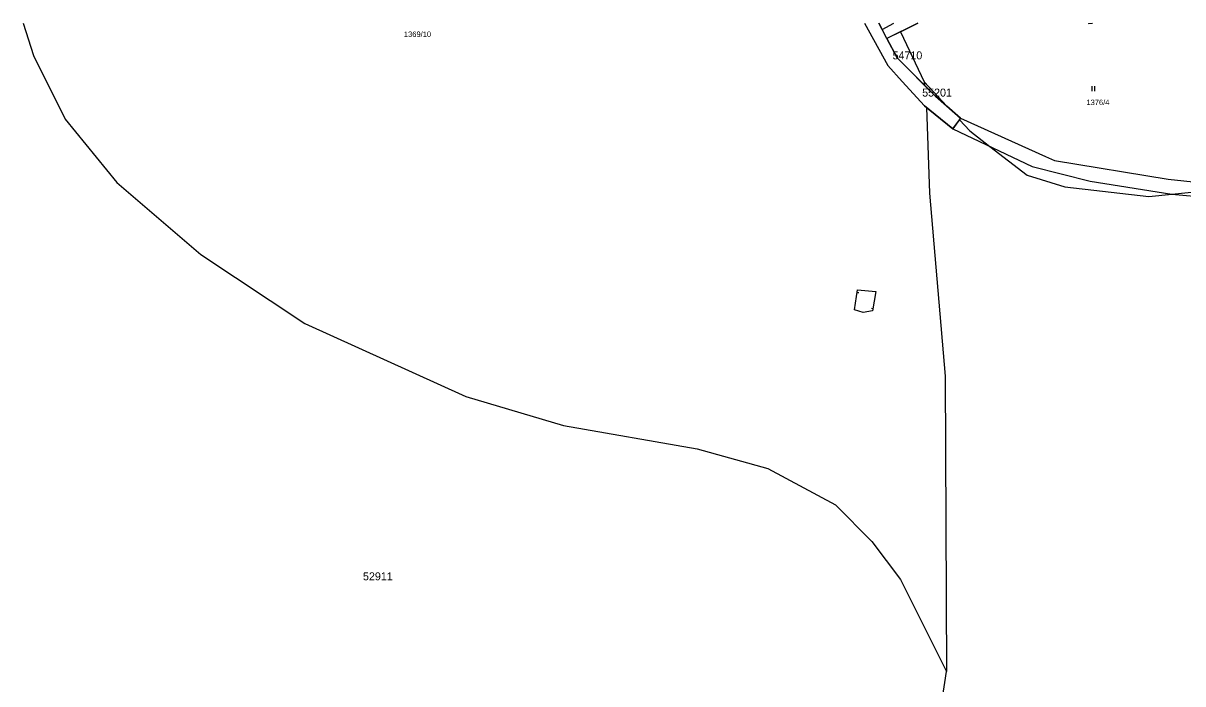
# Model space of a CAD drawing. Extents: x -779618 to -776429, y -1144546 to -1143350.
# Drawn here: x -778020.3 to -777658, y -1143556 to -1143349.7 of the extents above; entities that cross this region are included whole.
import ezdxf

# ---------------------------------------------------------------- set-up
doc = ezdxf.new("R2010")
doc.units = 0
for name, color, linetype in [('1', 7, 'Continuous'), ('11', 7, 'Continuous'), ('13', 7, 'Continuous'), ('2', 7, 'Continuous'), ('3', 7, 'Continuous')]:
    doc.layers.add(name, color=color, linetype=linetype)

msp = doc.modelspace()

# ---------------------------------------------------------------- linework, layer by layer
at = {"layer": '1'}
for p, q in [((-777757.4, -1143349.66), (-777750.19, -1143362.92)), ((-777751.91, -1143351.66), (-777752.97, -1143349.66)), ((-777751.91, -1143351.66), (-777748.24, -1143349.66)), ((-777750.42, -1143354.47), (-777751.91, -1143351.66)), ((-777740.8, -1143349.66), (-777750.42, -1143354.47)), ((-777687.5, -1143349.66), (-777687.46, -1143349.72)), ((-777687.46, -1143349.72), (-777686.25, -1143349.66)), ((-777747.24, -1143360.48), (-777750.42, -1143354.47)), ((-777747.24, -1143360.48), (-777743.71, -1143364.03)), ((-777745.65, -1143367.9), (-777750.19, -1143362.92)), ((-777743.71, -1143364.03), (-777735.3, -1143372.48)), ((-777738.74, -1143375.48), (-777745.65, -1143367.9)), ((-777735.3, -1143372.48), (-777727.4, -1143379.32)), ((-777735.4, -1143378.17), (-777738.74, -1143375.48)), ((-777729.89, -1143382.61), (-777735.4, -1143378.17)), ((-777727.4, -1143379.32), (-777729.89, -1143382.61)), ((-777727.4, -1143379.32), (-777700.87, -1143391.26)), ((-777729.89, -1143382.61), (-777705.1, -1143394.4)), ((-777700.87, -1143391.26), (-777698.07, -1143392.52)), ((-777705.1, -1143394.4), (-777686.94, -1143398.98)), ((-777698.07, -1143392.52), (-777662.61, -1143398.35)), ((-777686.94, -1143398.98), (-777661.39, -1143403.04)), ((-777662.61, -1143398.35), (-777644.06, -1143400.37)), ((-777661.39, -1143403.04), (-777640.98, -1143404.85))]:
    msp.add_line(p, q, dxfattribs=at)
at = {"layer": '11'}
for p, q in [((-777746.22, -1143352.37), (-777738.77, -1143368.02)), ((-777738.77, -1143368.02), (-777738.66, -1143369.1)), ((-777738.77, -1143368.02), (-777731.72, -1143375.58))]:
    msp.add_line(p, q, dxfattribs=at)
for points in [[(-778020.26, -1143349.66), (-778017.08, -1143359.78), (-778007.13, -1143379.58), (-777991.04, -1143399.45), (-777964.75, -1143421.85), (-777932.29, -1143443.46), (-777881.94, -1143466.27), (-777851.46, -1143475.36), (-777809.67, -1143482.62), (-777787.6, -1143488.75), (-777766.54, -1143500.14), (-777755.13, -1143511.53), (-777746.22, -1143523.38), (-777731.77, -1143552.16)], [(-777757.4, -1143349.66), (-777750.19, -1143362.92), (-777745.65, -1143367.9), (-777738.74, -1143375.48), (-777738.07, -1143376.02)], [(-777752.97, -1143349.66), (-777751.91, -1143351.66), (-777748.25, -1143349.66)], [(-777746.22, -1143352.37), (-777740.79, -1143349.66)], [(-777687.5, -1143349.66), (-777687.46, -1143349.72), (-777686.25, -1143349.66)], [(-777746.22, -1143352.37), (-777750.42, -1143354.47), (-777747.24, -1143360.48), (-777743.71, -1143364.03), (-777738.66, -1143369.1)], [(-777738.66, -1143369.1), (-777735.3, -1143372.48), (-777731.72, -1143375.58)], [(-777738.07, -1143376.02), (-777735.4, -1143378.17), (-777729.89, -1143382.61), (-777727.77, -1143379.81)], [(-777738.07, -1143376.02), (-777737.11, -1143402.78), (-777732.2, -1143459.88), (-777731.77, -1143552.16)], [(-777727.77, -1143379.81), (-777727.4, -1143379.32), (-777731.72, -1143375.58)], [(-777727.77, -1143379.81), (-777724.56, -1143383.26), (-777718.29, -1143388.13), (-777706.66, -1143397.15), (-777694.8, -1143400.8), (-777668.59, -1143403.77), (-777661.46, -1143403.03), (-777650.2, -1143401.86), (-777635.16, -1143401.86), (-777609.52, -1143396.6), (-777587.78, -1143392.14), (-777578.36, -1143390.89), (-777532.49, -1143384.83), (-777529.79, -1143384.69), (-777517.23, -1143384.06), (-777498.37, -1143386.29), (-777486.81, -1143386.56), (-777483.16, -1143386.65)], [(-777756.31, -1143612.29), (-777755.79, -1143611.67), (-777736.5, -1143577.24), (-777734.89, -1143572.06), (-777731.77, -1143552.16)]]:
    msp.add_lwpolyline(points, dxfattribs=at)
at = {"layer": '13'}
for p, q in [((-777760.57, -1143439.17), (-777759.6, -1143432.89)), ((-777759.73, -1143433.73), (-777759.24, -1143433.81)), ((-777759.6, -1143432.89), (-777753.88, -1143433.45)), ((-777753.88, -1143433.45), (-777754.92, -1143439.51)), ((-777754.81, -1143438.87), (-777755.3, -1143438.79)), ((-777757.9, -1143440.03), (-777760.57, -1143439.17)), ((-777754.92, -1143439.51), (-777757.9, -1143440.03))]:
    msp.add_line(p, q, dxfattribs=at)
at = {"layer": '3'}
for p, q in [((-777686.45, -1143369.37), (-777686.45, -1143370.87)), ((-777685.45, -1143370.87), (-777685.45, -1143369.37))]:
    msp.add_line(p, q, dxfattribs=at)

# ---------------------------------------------------------------- texts
at = {"layer": '11'}
for s, p in [('54710', (-777748.68, -1143360.95)), ('55201', (-777739.42, -1143372.58)), ('52911', (-777914.11, -1143523.67))]:
    msp.add_text(s, height=2.5, dxfattribs=at).set_placement(p)
at = {"layer": '2'}
for s, p in [('1369/10', (-777901.32, -1143353.95)), ('1376/4', (-777688.1, -1143375.23))]:
    msp.add_text(s, height=1.7, dxfattribs=at).set_placement(p)

doc.saveas('drawing.dxf')
